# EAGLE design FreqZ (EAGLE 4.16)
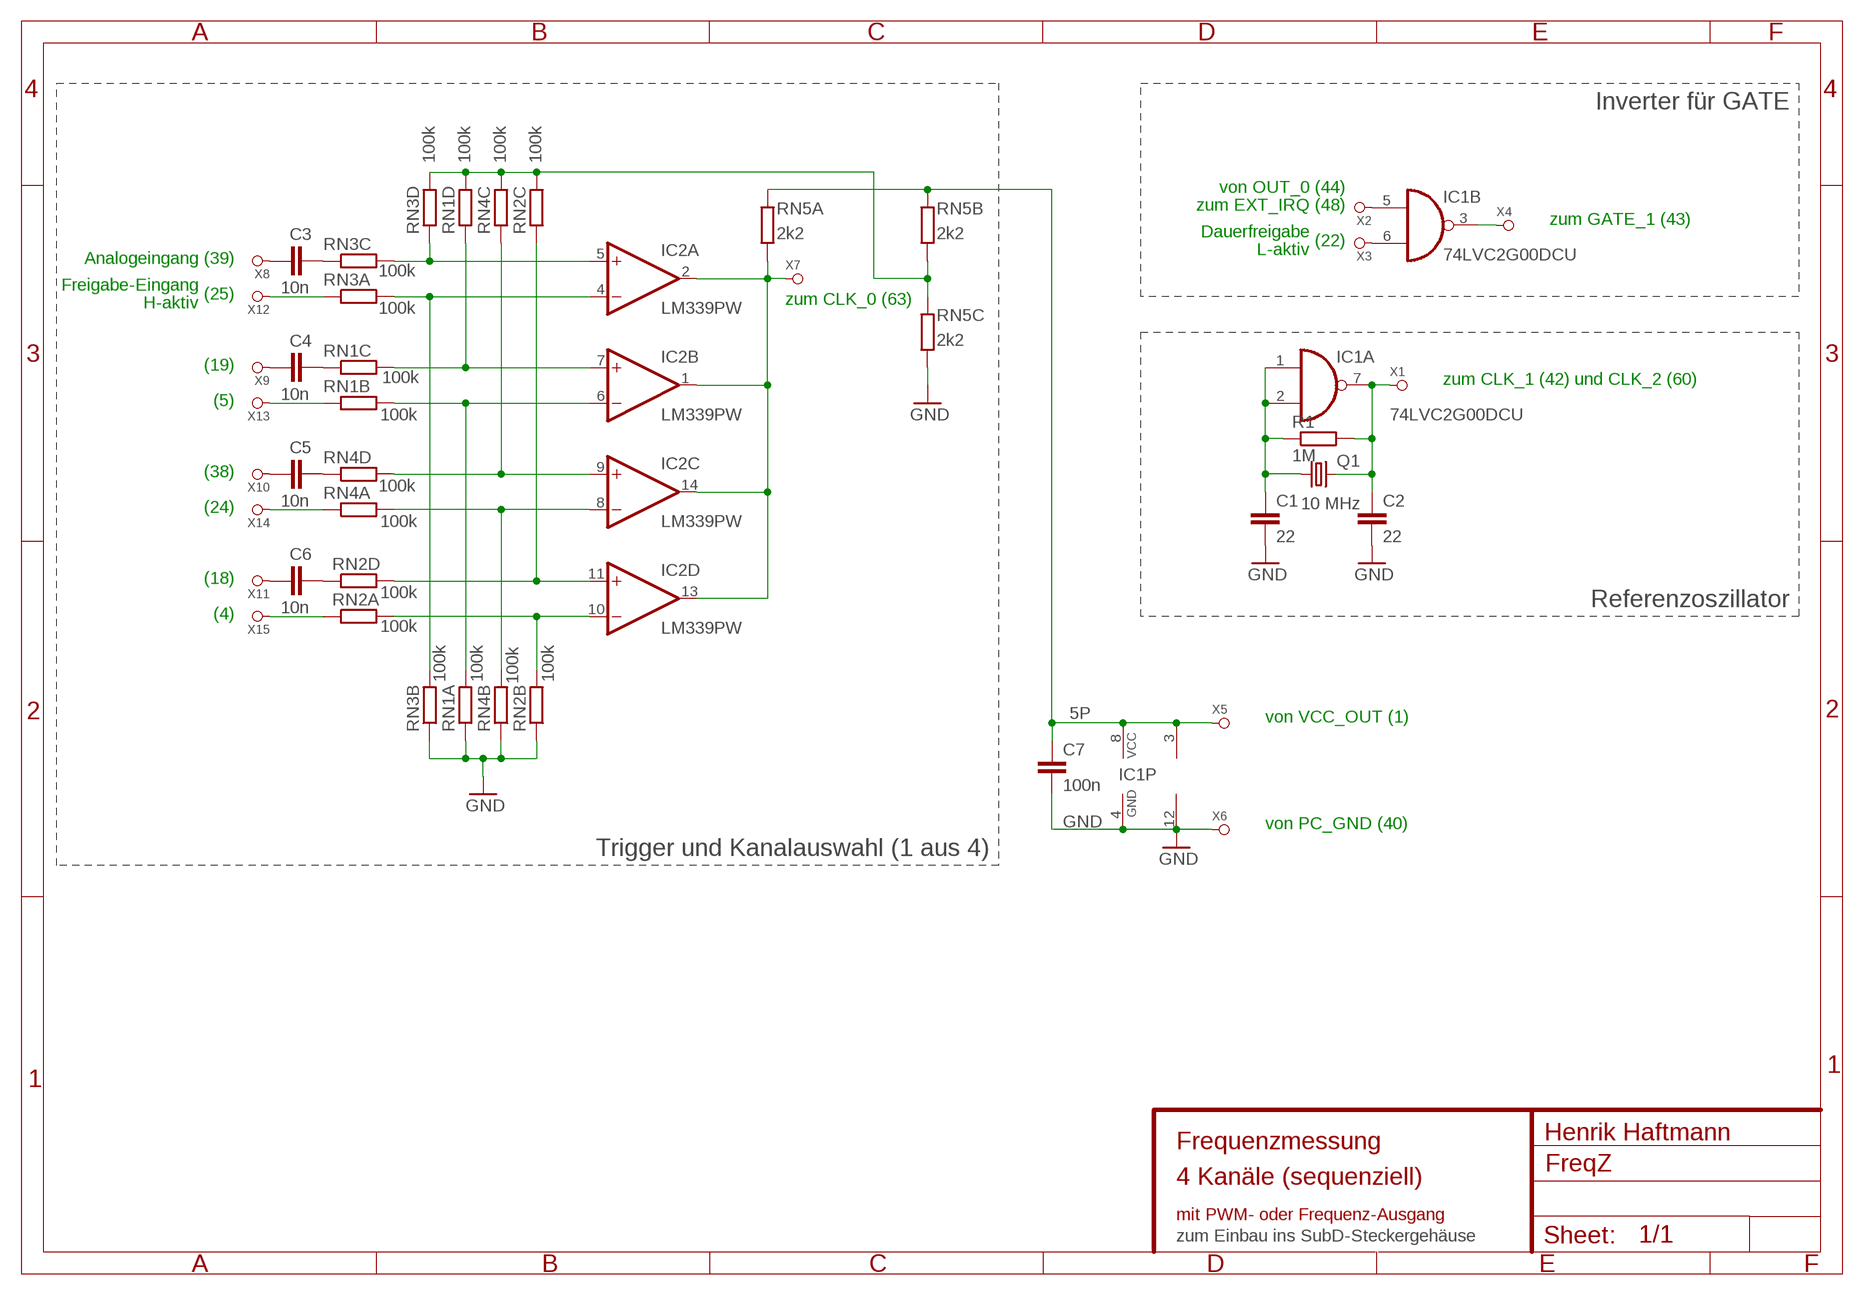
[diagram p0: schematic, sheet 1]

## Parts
C1  22  C-EUC0603K  [C0603K]
C2  22  C-EUC0603K  [C0603K]
C3  10n  C-EUC0603K  [C0603K]
C4  10n  C-EUC0603K  [C0603K]
C5  10n  C-EUC0603K  [C0603K]
C6  10n  C-EUC0603K  [C0603K]
C7  100n  C-EUC0603K  [C0603K]
IC1  74LVC2G00DCU  [DCU08]
IC2  LM339PW  [S14]
Q1  10 MHz  CRYSTALHC49U-V  [HC49U-V]
R1  1M  R-EU_R0603  [R0603]
RN1  100k  RN-4P1206  [R-4P]
RN2  100k  RN-4P1206  [R-4P]
RN3  100k  RN-4P1206  [R-4P]
RN4  100k  RN-4P1206  [R-4P]
RN5  2k2  RN-4P1206  [R-4P]
X1  PAD  [PAD]
X2  PAD  [PAD]
X3  PAD  [PAD]
X4  PAD  [PAD]
X5  PAD  [PAD]
X6  PAD  [PAD]
X7  PAD  [PAD]
X8  PAD  [PAD]
X9  PAD  [PAD]
X10  PAD  [PAD]
X11  PAD  [PAD]
X12  PAD  [PAD]
X13  PAD  [PAD]
X14  PAD  [PAD]
X15  PAD  [PAD]

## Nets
2P5: RN1.4 RN2.3 RN3.4 RN4.3 RN5.2 RN5.3
5P: C7.1 IC1.8(P:VCC) IC2.3(P:V+) RN5.7 RN5.8 X5.1
GND: C1.2 C2.2 C7.2 IC1.4(P:GND) IC2.12(P:GND) RN1.1 RN2.2 RN3.2 RN4.2 RN5.6 X6.1
N$1: C1.1 IC1.1(A:I0) IC1.2(A:I1) Q1.1 R1.1
N$2: IC1.5(B:I0) X2.1
N$3: C3.1 X8.1
N$4: IC1.6(B:I1) X3.1
N$5: IC2.1(B:OUT) IC2.2(A:OUT) IC2.13(D:OUT) IC2.14(C:OUT) RN5.1 X7.1
N$6: C2.1 IC1.7(A:O) Q1.2 R1.2 X1.1
N$7: IC1.3(B:O) X4.1
N$8: C3.2 RN3.3
N$10: RN2.1 X15.1
N$11: RN4.1 X14.1
N$12: C4.2 RN1.3
N$13: C4.1 X9.1
N$14: C5.1 X10.1
N$15: C5.2 RN4.4
N$16: C6.1 X11.1
N$17: C6.2 RN2.4
N$18: IC2.5(A:+IN) RN3.5 RN3.6
N$19: RN3.1 X12.1
N$20: IC2.4(A:-IN) RN3.7 RN3.8
N$21: IC2.7(B:+IN) RN1.5 RN1.6
N$22: RN1.2 X13.1
N$23: IC2.6(B:-IN) RN1.7 RN1.8
N$24: IC2.9(C:+IN) RN4.5 RN4.6
N$25: IC2.8(C:-IN) RN4.7 RN4.8
N$26: IC2.11(D:+IN) RN2.5 RN2.6
N$27: IC2.10(D:-IN) RN2.7 RN2.8
Unconnected: RN5.4 RN5.5

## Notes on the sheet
- Inverter für GATE
- von OUT_0 (44)
- zum EXT_IRQ (48)
- Dauerfreigabe | zum GATE_1 (43)
- (22)
- L-aktiv
- Analogeingang (39)
- Freigabe-Eingang
- (25)
- H-aktiv
- zum CLK_0 (63)
- (19)
- zum CLK_1 (42) und CLK_2 (60)
- (5)
- (38)
- (24)
- (18)
- Referenzoszillator
- (4)
- von VCC_OUT (1)
- von PC_GND (40)
- Trigger und Kanalauswahl (1 aus 4)
- Henrik Haftmann
- Frequenzmessung
- 4 Kanäle (sequenziell)
- mit PWM- oder Frequenz-Ausgang
- zum Einbau ins SubD-Steckergehäuse

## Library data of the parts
C1-C7 = rcl:C-EU: CAPACITOR, European symbol
IC1 = DiffV:74*2G00: Dual 2-input NAND gate AUC = 3,3 V maximal!
IC2 = DiffV:LM339: Low Power Low Offset Voltage Quad Comparators with open collector; LM139/LM239/LM339/LM2901/LM3302
Q1 = crystal:CRYSTAL: CRYSTAL
R1 = rcl:R-EU_: RESISTOR, European symbol
RN1-RN5 = DiffV:RN-4P: Widerstandsnetzwerk 4 Parallel
X1-X15 = DiffV:PAD

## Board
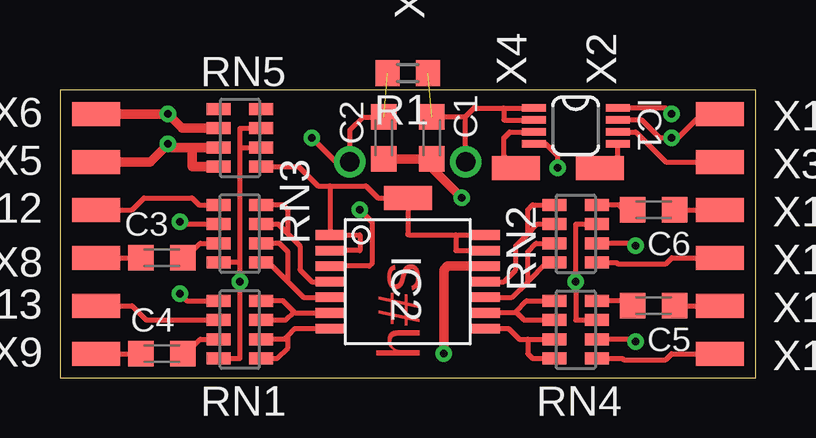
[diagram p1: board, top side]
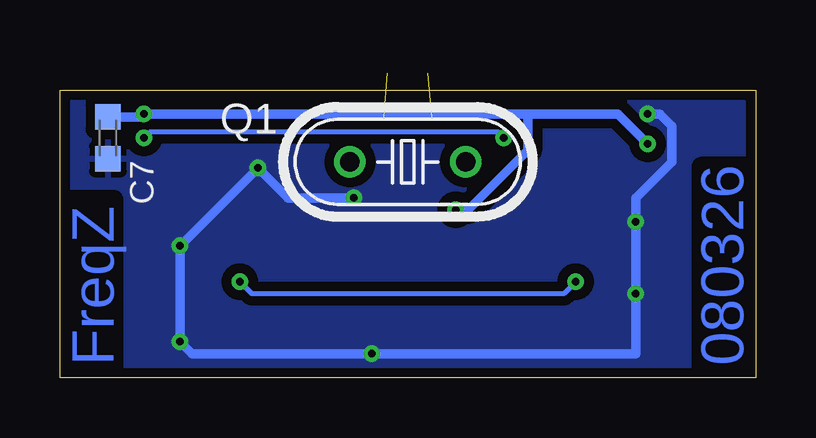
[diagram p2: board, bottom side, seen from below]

Size 29 x 12 mm. Coordinates in mm from the lower left corner, seen from the top.
Outline: 0,0 29,0 29,12 0,12 0,0
Copper layers (1*16): Top 0.035mm / dielectric 1.5mm / Bottom 0.035mm
Design rules "Felber": minimum track width 0.2mm, minimum drill 0.3mm, track to track 0.2mm, track to pad 0.2mm, pad to pad 0.2mm, via to via 0.2mm, smd to smd 0mil, copper to edge 0.2mm, drill to drill 0.3mm, minimum pad ring 10mil, minimum via ring 8mil, stop-mask expansion 4mil, vias tented up to drill 0.4mm, thermal gap 10mil

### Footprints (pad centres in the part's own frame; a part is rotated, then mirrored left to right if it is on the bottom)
C0603K = smd 1.05 x 1.08: 1 -0.875,0; 2 0.875,0
DCU08 = smd 0.3 x 1: 1 -0.75,-1.75; 2 -0.25,-1.75; 3 0.25,-1.75; 4 0.75,-1.75; 5 0.75,1.75; 6 0.25,1.75; 7 -0.25,1.75; 8 -0.75,1.75
S14 = smd 0.4 x 1.2: 1 -1.95,-3.25; 2 -1.3,-3.25; 3 -0.65,-3.25; 4 0,-3.25; 5 0.65,-3.25; 6 1.3,-3.25; 7 1.95,-3.25; 8 1.95,3.25; 9 1.3,3.25; 10 0.65,3.25; 11 0,3.25; 12 -0.65,3.25; 13 -1.3,3.25; 14 -1.95,3.25
HC49U-V = drill 0.813 round: 1 -2.413,0; 2 2.413,0
R0603 = smd 1 x 1.1: 1 -0.85,0; 2 0.85,0
R-4P = smd 0.5 x 1: 1 -1.2,-0.88; 2 -0.4,-0.88; 3 0.4,-0.88; 4 1.2,-0.88; 5 1.2,0.88; 6 0.4,0.88; 7 -0.4,0.88; 8 -1.2,0.88
PAD = smd 1 x 2: 1 0,0

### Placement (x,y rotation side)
C1  15.5,10 270 top
C2  13.5,10 270 top
C3  4.25,5 0 top
C4  4.25,1 0 top
C5  24.75,3 180 top
C6  24.75,7 180 top
C7  27,10 270 bottom
IC1  21.5,10.5 270 top
IC2  14.5,4 270 top
Q1  14.5,9 0 bottom
R1  14.5,12.7 180 top
RN1  7.5,2 270 top
RN2  21.5,6 90 top
RN3  7.5,6 270 top
RN4  21.5,2 90 top
RN5  7.5,10 90 top
X1  27.5,11 270 top
X2  22.5,8.75 270 top
X3  27.5,9 270 top
X4  19,8.75 270 top
X5  1.5,9 90 top
X6  1.5,11 270 top
X7  14.5,7.5 270 top
X8  1.5,5 270 top
X9  1.5,1 270 top
X10  27.5,3 270 top
X11  27.5,7 270 top
X12  1.5,7 270 top
X13  1.5,3 270 top
X14  27.5,1 270 top
X15  27.5,5 270 top

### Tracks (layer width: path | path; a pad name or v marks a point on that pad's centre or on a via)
2P5  (via drill 0.3)
  Top 0.2: RN1.4 7.5,0.8 v7.5,4 7.5,4.75 | RN3.4 7.5,4.8 7.5,4.75 | RN5.3 7.5,10.4 7.5,9.5 | 7.5,4.75 7.5,9.5 | RN5.2 7.5,9.6 7.5,9.5 | RN2.3 21.5,6.4 v21.5,4 21.5,2.4 RN4.3
  Bottom 0.2: v21.5,4 21,3.5 8,3.5 v7.5,4
5P  (via drill 0.3)
  Top 0.2: v4.5,9.75 4.65,9.6 | 5.49,9.6 5.5,9.6 | IC1.8 25.25,11.25 v25.5,11 | v12.5,7 13,6.5 13,4.75 12.9,4.65 IC2.3
  Top 0.4: 4.65,9.6 5.49,9.6 RN5.7 | v4.5,9.75 3.75,9 X5.1 | RN5.8 5.5,8.8 5.5,9.6
  Bottom 0.4: v12.5,7 12,7 9.5,9.5 9.5,11 | 9.5,11 v25.5,11 25.62,10.88 C7.1 | 9.5,11 5.75,11 v4.5,9.75
GND  (via drill 0.3)
  Top 0.2: RN1.1 5.3,3.2 v5,3.5 | RN3.2 5.1,6.4 v5,6.5 | IC1.4 20.25,9.75 20.75,9.25 v20.75,8.75 | RN2.2 23.9,5.6 v24,5.5 | RN4.2 23.9,1.6 v24,1.5 | 15.5,9.25 C1.2 15.5,8.75
  Top 0.4: RN5.6 5.1,10.4 v4.5,11 X6.1 | IC2.12 16.15,4.65 16,4.5 v16,1 | C1.2 C2.2 | v16.75,7.5 15.5,8.75
  Bottom 0.4: v4.5,11 4,11 3.5,10.5 3.5,9 5,7.5 v5,6.5 v5,3.5 5,1 v16,1 23.5,1 v24,1.5 v24,5.5 v20.75,8.75 19.5,7.5 v16.75,7.5
  pour Bottom (isolate 0.4): 0.5,11.5 28.5,11.5 28.5,0.5 0.5,0.5
N$1  (1 unrouted)
  Top 0.2: 18.5,11.25 IC1.1 | 18.5,11.25 18.5,10.75 IC1.2 | Q1.1 16.91,10.91 17,11 | 17,11 17.25,11.25 18.5,11.25 | C1.1 16.88,10.88 17,11
N$2
  Top 0.2: IC1.5 23.25,9.25 22.75,8.75 X2.1
N$3
  Top 0.2: X8.1 C3.1
N$4
  Top 0.2: IC1.6 24,10.25 25.25,9 X3.1
N$5
  Top 0.2: RN5.1 9.95,8.8 10.75,8 11.25,8 | 11.25,8 12.75,8 13.25,7.5 X7.1 14.5,6 | 16.5,5.95 14.55,5.95 14.5,6 | 16.5,5.95 IC2.14 | IC2.13 16.5,5.3 16.5,5.95 | 14.5,6 14.5,5.95 | IC2.2 12.5,5.3 12.5,5.95 IC2.1 11.25,8
N$6  (via drill 0.3)  (1 unrouted)
  Top 0.2: IC1.7 24.25,10.75 25,10 v25.5,10 25.75,10 26.75,11 X1.1 | v10.5,10 11.5,9 Q1.2 12.09,10.34 12.62,10.88 C2.1
  Bottom 0.2: v10.5,10 10.75,10.25 25.25,10.25 v25.5,10
N$7
  Top 0.2: IC1.3 18.75,10.25 18.5,10 18.5,9.25 X4.1
N$8
  Top 0.2: C3.2 5.25,5 5.85,5.6 RN3.3
N$10
  Top 0.2: RN2.1 23.2,4.8 23.25,4.75 25.25,4.75 25.5,5 X15.1
N$11
  Top 0.2: RN4.1 23.45,0.8 23.5,0.75 25.25,0.75 25.5,1 X14.1
N$12
  Top 0.2: C4.2 5.25,1 5.85,1.6 RN1.3
N$13
  Top 0.2: X9.1 C4.1
N$14
  Top 0.2: C5.1 X10.1
N$15
  Top 0.2: C5.2 23.75,3 23.55,3.2 RN4.4
N$16
  Top 0.2: C6.1 X11.1
N$17
  Top 0.2: C6.2 23.5,7 23.3,7.2 RN2.4
N$18
  Top 0.2: IC2.5 10.15,3.35 9.5,4 | RN3.5 8.7,4.8 9.5,4 | RN3.6 9.15,5.6 9.5,5.25 9.5,4
N$19
  Top 0.2: RN3.1 5.8,7.2 5.5,7.5 3.5,7.5 3,7 X12.1
N$20
  Top 0.2: RN3.7 9.1,6.4 9.5,6 | 9.5,6 10,5.5 10,4.5 10.5,4 IC2.4 | RN3.8 9.3,7.2 9.5,7 9.5,6
N$21
  Top 0.2: IC2.7 9.8,2.05 9.5,1.75 | 9.5,1.75 9.5,1.25 9.05,0.8 RN1.5 | RN1.6 9.35,1.6 9.5,1.75
N$22
  Top 0.2: RN1.2 3.6,2.4 3,3 X13.1
N$23
  Top 0.2: IC2.6 9.8,2.7 9.75,2.75 | RN1.8 9.3,3.2 9.75,2.75 | RN1.7 9.4,2.4 9.75,2.75
N$24
  Top 0.2: IC2.9 18.95,2.7 19,2.75 | RN4.5 19.45,3.2 19,2.75 | RN4.6 19.35,2.4 19,2.75
N$25
  Top 0.2: 19.5,1.6 19.15,1.6 18.7,2.05 IC2.8 | 19.5,1.6 RN4.7 | RN4.8 19.7,0.8 19.5,1 19.5,1.6
N$26
  Top 0.2: RN2.6 19.9,6.4 19.5,6 | 19.5,6 19,5.5 19,4.5 18.5,4 IC2.11 | RN2.5 19.7,7.2 19.5,7 19.5,6
N$27
  Top 0.2: RN2.8 20.3,4.8 19.5,4 | IC2.10 18.85,3.35 19.5,4 | RN2.7 19.85,5.6 19.5,5.25 19.5,4

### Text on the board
Top: h#s
Bottom: 080326 | FreqZ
